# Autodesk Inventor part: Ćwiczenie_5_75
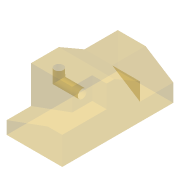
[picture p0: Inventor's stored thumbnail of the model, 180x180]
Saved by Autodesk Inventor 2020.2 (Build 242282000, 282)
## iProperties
Created: 2005-08
Part Number: Ćwiczenie_5_75
Document SubType Name: Modeling
Designer: F.Stasiak
Manufacturer: Standard
Standards Organization: Custom
Density: 1 g/cm^3
Material: Ogólny
Appearance: Domyślna
Manager: www.cadconsulting.pl
Company: Fabian Stasiak CAD Consulting
Author: F.Stasiak
Subject: Zbiór ćwiczeń. Autodesk Inventor 2020. Kurs podstawowy
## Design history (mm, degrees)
derived "PunktyK.ipt"
node "Korpusy bryłowe"
node "Korpusy powierzchniowe"
feature "Pozyskana bryła konstrukcyjna1"
body "Srf1"
